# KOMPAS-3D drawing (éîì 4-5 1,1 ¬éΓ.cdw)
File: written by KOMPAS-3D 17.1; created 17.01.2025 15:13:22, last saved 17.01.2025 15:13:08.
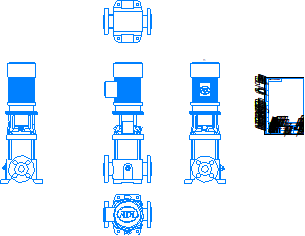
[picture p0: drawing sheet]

Sheet 1: A4, portrait

Title block, sheet 1: name: ВМН 4-5 1,1 кВт; designation: ВМН 4-5 1,1 кВт; sheets: 1; sheet format: A4; stored path: \\adlc.lan\data\АДЛ_ПКД\3D-модели\ADL production\Насосы ГРАНПАМП\Насосы ВМН\ВМН4\KOMPAS 2D\ВМН 4-5 1,1 кВт.cdw

Views: Вид 1, Спереди, Проекционный вид 2, Проекционный вид 3, Проекционный вид 4, Проекционный вид 5
Referenced files in \\adlc.lan\data\АДЛ_ПКД\3D-модели\ADL production\Насосы ГРАНПАМП\Насосы ВМН\ВМН4\KOMPAS 3D\: ВМН 4-5 1,1 кВт.m3d
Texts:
  Andrey
  АДЛ
Dimensions and other numbers on the sheet: 1:1; 1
